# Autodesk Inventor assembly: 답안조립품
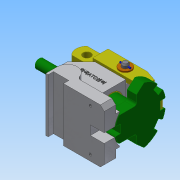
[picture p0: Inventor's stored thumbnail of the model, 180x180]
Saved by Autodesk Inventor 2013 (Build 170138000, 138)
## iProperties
Created: 2016-11
Part Number: 답안조립품
Document SubType Name: Assembly
Designer: Administrator
Author: Administrator
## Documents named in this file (8)
- C:\Users\Administrator\Desktop\461108V1017\답안조립품.iam
- C:\Users\Administrator\Desktop\461108V1017\본체.ipt
- C:\Users\Administrator\Desktop\461108V1017\부시.ipt
- C:\Users\Administrator\Desktop\461108V1017\분할축.ipt
- C:\Users\Administrator\Desktop\461108V1017\클레비스핀.ipt
- C:\Users\Administrator\Desktop\461108V1017\원통형핀.ipt
- C:\Users\Administrator\Desktop\461108V1017\와셔.ipt
- C:\Users\Administrator\Desktop\461108V1017\분할대.ipt
